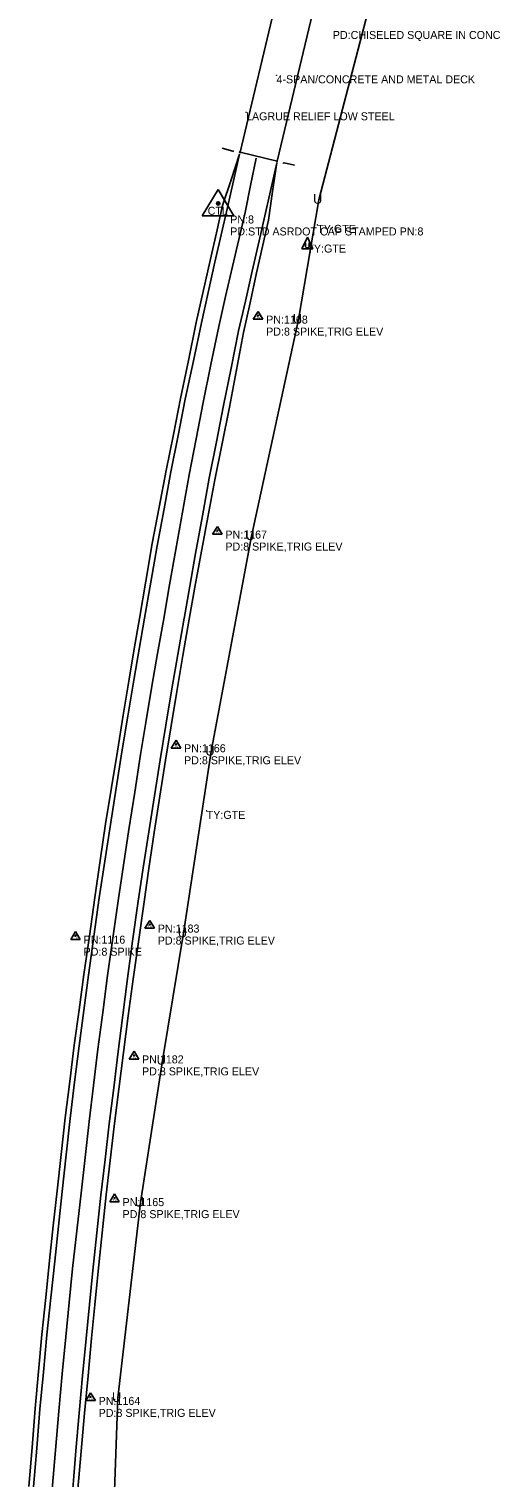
# Model space of a CAD drawing. Extents: x 1445297 to 1476720, y 2042269 to 2057889.
# Drawn here: x 1445689 to 1445983, y 2053749 to 2054654 of the extents above; entities that cross this region are included whole.
import ezdxf

# ---------------------------------------------------------------- set-up
doc = ezdxf.new("R2010")
doc.units = 0
for name, color, linetype in [('S_BRIDGE', 7, 'Continuous'), ('S_EDGE_PAVEMENT', 7, 'Continuous'), ('S_FIBER_OPTIC_CABLE_ANNOT', 7, 'Continuous'), ('S_MSC_PT_SYM', 7, 'Continuous'), ('S_PAVEMENT_CROWN', 7, 'Continuous'), ('S_PRIMARY_CTL', 7, 'Continuous'), ('S_PRIMARY_CTL_ANNOT', 7, 'Continuous'), ('S_SECONDARY_CTL', 7, 'Continuous'), ('S_SECONDARY_CTL_ANNOT', 7, 'Continuous'), ('S_SHOULDER', 7, 'Continuous'), ('S_STR_PT_SYM', 7, 'Continuous'), ('S_SURVEY_TEXT_ANNOT', 7, 'Continuous'), ('S_UNDERGROUND_CABLE', 7, 'Continuous'), ('S_UTILITY_POLE', 7, 'Continuous'), ('S_UTILITY_POLE_ANNOT', 7, 'Continuous'), ('S_UTL_PT_SYM', 7, 'Continuous'), ('S_WALL', 7, 'Continuous')]:
    doc.layers.add(name, color=color, linetype=linetype)

msp = doc.modelspace()

# ---------------------------------------------------------------- linework, layer by layer
at = {"layer": 'S_BRIDGE'}
for p, q in [((1445820.81, 2054577.05), (1445844.02, 2054674.24)), ((1445867.36, 2054668.87), (1445844.01, 2054571.43)), ((1445844.01, 2054571.43), (1445820.81, 2054577.05))]:
    msp.add_line(p, q, dxfattribs=at)
at = {"layer": 'S_EDGE_PAVEMENT'}
for points in [[(1445691.76, 2053742.83), (1445693.79, 2053767.11), (1445695.82, 2053791.4), (1445698.01, 2053814.6), (1445700.19, 2053837.81), (1445702.62, 2053860.93), (1445705.04, 2053884.05), (1445707.31, 2053905.74), (1445709.58, 2053927.43), (1445712.13, 2053950.31), (1445714.68, 2053973.19), (1445717.46, 2053995.81), (1445720.23, 2054018.42), (1445723.13, 2054040.58), (1445726.03, 2054062.73), (1445729.45, 2054086.9), (1445732.86, 2054111.06), (1445736.35, 2054133.98), (1445739.85, 2054156.89), (1445743.42, 2054179.52), (1445746.99, 2054202.16), (1445750.74, 2054224.55), (1445754.48, 2054246.94), (1445757.79, 2054266.34), (1445761.09, 2054285.73), (1445765.04, 2054308.35), (1445768.99, 2054330.97), (1445773.31, 2054354.13), (1445777.62, 2054377.29), (1445782.09, 2054399.97), (1445786.57, 2054422.64), (1445791.69, 2054446.54), (1445796.81, 2054470.43), (1445800.94, 2054489.32), (1445805.06, 2054508.2), (1445808.99, 2054525.32), (1445812.92, 2054542.44), (1445816.72, 2054559.08), (1445820.53, 2054575.72)], [(1445716.28, 2053741.76), (1445718.26, 2053765.38), (1445720.25, 2053788.99), (1445722.45, 2053812.32), (1445724.66, 2053835.65), (1445726.77, 2053856.9), (1445728.89, 2053878.15), (1445731.41, 2053901.64), (1445733.92, 2053925.12), (1445736.5, 2053947.43), (1445739.07, 2053969.74), (1445741.86, 2053992.34), (1445744.65, 2054014.94), (1445747.53, 2054037.75), (1445750.41, 2054060.55), (1445753.68, 2054084.02), (1445756.94, 2054107.48), (1445760.33, 2054129.83), (1445763.73, 2054152.17), (1445767.28, 2054174.76), (1445770.84, 2054197.34), (1445774.46, 2054218.89), (1445778.09, 2054240.44), (1445781.98, 2054263.07), (1445785.88, 2054285.69), (1445785.88, 2054285.51), (1445789.47, 2054305.86), (1445793.06, 2054326.22), (1445797.32, 2054349.71), (1445801.57, 2054373.2), (1445806.02, 2054395.94), (1445810.46, 2054418.68), (1445815.19, 2054441.98), (1445819.93, 2054465.28), (1445824.21, 2054483.92), (1445828.49, 2054502.57), (1445832.23, 2054518.93), (1445835.97, 2054535.29), (1445839.85, 2054552.8), (1445843.73, 2054570.31)]]:
    msp.add_lwpolyline(points, dxfattribs=at)
at = {"layer": 'S_MSC_PT_SYM'}
for points in [[(1445843.6, 2054625.03), (1445843.6, 2054625.08), (1445843.6, 2054625.03), (1445843.55, 2054625.03), (1445843.6, 2054625.03), (1445843.6, 2054624.98), (1445843.6, 2054625.03), (1445843.65, 2054625.03)], [(1445824.57, 2054601.93), (1445824.57, 2054601.98), (1445824.57, 2054601.93), (1445824.52, 2054601.93), (1445824.57, 2054601.93), (1445824.57, 2054601.88), (1445824.57, 2054601.93), (1445824.62, 2054601.93)]]:
    msp.add_lwpolyline(points, dxfattribs=at)
at = {"layer": 'S_PAVEMENT_CROWN'}
msp.add_lwpolyline([(1445703.34, 2053741.56), (1445705.43, 2053765.89), (1445707.51, 2053790.22), (1445709.73, 2053813.46), (1445711.95, 2053836.7), (1445714.04, 2053858.03), (1445716.12, 2053879.35), (1445718.79, 2053902.87), (1445721.46, 2053926.38), (1445723.99, 2053948.75), (1445726.53, 2053971.13), (1445729.22, 2053993.76), (1445731.92, 2054016.4), (1445734.99, 2054039.43), (1445738.06, 2054062.47), (1445741.35, 2054085.76), (1445744.65, 2054109.05), (1445747.97, 2054131.36), (1445751.28, 2054153.67), (1445754.99, 2054177.09), (1445758.69, 2054200.5), (1445762.18, 2054221.87), (1445765.67, 2054243.23), (1445769.32, 2054263.74), (1445772.97, 2054284.25), (1445776.79, 2054306.53), (1445780.61, 2054328.8), (1445784.86, 2054352.04), (1445789.11, 2054375.29), (1445793.45, 2054397.89), (1445797.79, 2054420.5), (1445802.67, 2054444.25), (1445807.54, 2054468), (1445811.79, 2054486.77), (1445816.03, 2054505.54), (1445819.99, 2054522.37), (1445823.94, 2054539.2), (1445827.38, 2054556.24), (1445830.82, 2054573.28)], dxfattribs=at)
at = {"layer": 'S_PRIMARY_CTL'}
for p, q in [((1445807.18, 2054553.65), (1445797.14, 2054537.14)), ((1445807.18, 2054553.65), (1445817, 2054537.14)), ((1445797.14, 2054537.14), (1445817, 2054537.14))]:
    msp.add_line(p, q, dxfattribs=at)
for radius in [1.04, 0.609, 0.344]:
    msp.add_circle((1445807.18, 2054544.95), radius, dxfattribs=at)
at = {"layer": 'S_SECONDARY_CTL'}
for p, q in [((1445832.14, 2054477.5), (1445829.13, 2054472.55)), ((1445832.14, 2054477.5), (1445835.08, 2054472.55)), ((1445829.13, 2054472.55), (1445835.08, 2054472.55)), ((1445806.66, 2054343.15), (1445803.65, 2054338.2)), ((1445806.66, 2054343.15), (1445809.61, 2054338.2)), ((1445803.65, 2054338.2), (1445809.61, 2054338.2)), ((1445780.83, 2054209.59), (1445777.82, 2054204.64)), ((1445780.83, 2054209.59), (1445783.77, 2054204.64)), ((1445777.82, 2054204.64), (1445783.77, 2054204.64)), ((1445764.43, 2054096.92), (1445761.42, 2054091.97)), ((1445764.43, 2054096.92), (1445767.38, 2054091.97)), ((1445718.06, 2054089.97), (1445715.05, 2054085.01)), ((1445718.06, 2054089.97), (1445721.01, 2054085.01)), ((1445761.42, 2054091.97), (1445767.38, 2054091.97)), ((1445715.05, 2054085.01), (1445721.01, 2054085.01)), ((1445754.58, 2054015.16), (1445751.57, 2054010.21)), ((1445754.58, 2054015.16), (1445757.53, 2054010.21)), ((1445751.57, 2054010.21), (1445757.53, 2054010.21)), ((1445742.4, 2053925.95), (1445739.39, 2053921)), ((1445742.4, 2053925.95), (1445745.35, 2053921)), ((1445739.39, 2053921), (1445745.35, 2053921)), ((1445727.46, 2053801.74), (1445724.45, 2053796.79)), ((1445727.46, 2053801.74), (1445730.41, 2053796.79)), ((1445724.45, 2053796.79), (1445730.41, 2053796.79))]:
    msp.add_line(p, q, dxfattribs=at)
for centre, radius in [((1445832.14, 2054474.89), 0.311), ((1445832.14, 2054474.89), 0.183), ((1445832.14, 2054474.89), 0.103), ((1445806.66, 2054340.54), 0.311), ((1445806.66, 2054340.54), 0.183), ((1445806.66, 2054340.54), 0.103), ((1445780.83, 2054206.98), 0.311), ((1445780.83, 2054206.98), 0.183), ((1445780.83, 2054206.98), 0.103), ((1445718.06, 2054087.36), 0.311), ((1445718.06, 2054087.36), 0.183), ((1445718.06, 2054087.36), 0.103), ((1445764.43, 2054094.31), 0.311), ((1445764.43, 2054094.31), 0.183), ((1445764.43, 2054094.31), 0.103), ((1445754.58, 2054012.55), 0.311), ((1445754.58, 2054012.55), 0.183), ((1445754.58, 2054012.55), 0.103), ((1445742.4, 2053923.34), 0.311), ((1445742.4, 2053923.34), 0.183), ((1445742.4, 2053923.34), 0.103), ((1445727.46, 2053799.13), 0.311), ((1445727.46, 2053799.13), 0.183), ((1445727.46, 2053799.13), 0.103)]:
    msp.add_circle(centre, radius, dxfattribs=at)
at = {"layer": 'S_SHOULDER'}
for points in [[(1445688.92, 2053743.09), (1445690.9, 2053767.46), (1445692.87, 2053791.84), (1445694.95, 2053814.95), (1445697.04, 2053838.06), (1445699.4, 2053861.24), (1445701.77, 2053884.42), (1445704.11, 2053906.12), (1445706.46, 2053927.81), (1445709.02, 2053950.68), (1445711.57, 2053973.55), (1445714.38, 2053996.19), (1445717.19, 2054018.84), (1445720.23, 2054040.92), (1445723.28, 2054063), (1445726.68, 2054087.14), (1445730.07, 2054111.29), (1445733.44, 2054134.32), (1445736.81, 2054157.34), (1445740.49, 2054180.06), (1445744.16, 2054202.77), (1445747.85, 2054225.17), (1445751.54, 2054247.57), (1445754.73, 2054266.56), (1445757.93, 2054285.54), (1445761.96, 2054308.98), (1445765.98, 2054332.42), (1445770.34, 2054355.25), (1445774.7, 2054378.08), (1445779.2, 2054400.61), (1445783.71, 2054423.14), (1445788.53, 2054446.82), (1445793.36, 2054470.5), (1445797.72, 2054489.9), (1445802.08, 2054509.3), (1445806.02, 2054526.54), (1445809.97, 2054543.78), (1445815.25, 2054559.75), (1445820.53, 2054575.72)], [(1445719.56, 2053741.42), (1445721.59, 2053765.14), (1445723.62, 2053788.86), (1445725.84, 2053812.3), (1445728.06, 2053835.73), (1445730.08, 2053856.75), (1445732.09, 2053877.77), (1445734.62, 2053901.63), (1445737.15, 2053925.5), (1445739.65, 2053946.91), (1445742.15, 2053968.32), (1445745.03, 2053991.37), (1445747.92, 2054014.42), (1445750.98, 2054037.27), (1445754.05, 2054060.11), (1445757.34, 2054083.59), (1445760.63, 2054107.07), (1445763.91, 2054129.42), (1445767.18, 2054151.77), (1445770.68, 2054174.46), (1445774.17, 2054197.14), (1445777.75, 2054218.57), (1445781.34, 2054239.99), (1445785.14, 2054262.54), (1445788.94, 2054285.1), (1445792.65, 2054305.25), (1445796.36, 2054325.39), (1445800.68, 2054348.84), (1445805, 2054372.29), (1445809.67, 2054394.98), (1445814.33, 2054417.66), (1445818.71, 2054440.96), (1445823.09, 2054464.25), (1445827.11, 2054482.89), (1445831.13, 2054501.52), (1445834.9, 2054518.04), (1445838.67, 2054534.56), (1445841.2, 2054552.44), (1445843.73, 2054570.31)]]:
    msp.add_lwpolyline(points, dxfattribs=at)
at = {"layer": 'S_STR_PT_SYM'}
for points in [[(1445820.81, 2054577.05), (1445820.81, 2054577.55), (1445820.81, 2054577.05), (1445820.31, 2054577.05), (1445820.81, 2054577.05), (1445820.81, 2054576.55), (1445820.81, 2054577.05), (1445821.31, 2054577.05)], [(1445844.01, 2054571.43), (1445844.01, 2054571.93), (1445844.01, 2054571.43), (1445843.51, 2054571.43), (1445844.01, 2054571.43), (1445844.01, 2054570.93), (1445844.01, 2054571.43), (1445844.51, 2054571.43)]]:
    msp.add_lwpolyline(points, dxfattribs=at)
at = {"layer": 'S_UNDERGROUND_CABLE'}
for p, q in [((1445870.09, 2054547.32), (1445935.62, 2054798.44)), ((1445857.39, 2054472.48), (1445870.09, 2054547.32)), ((1445827.89, 2054337.12), (1445857.39, 2054472.48)), ((1445802.76, 2054202.49), (1445827.89, 2054337.12)), ((1445785.57, 2054088.88), (1445802.76, 2054202.49)), ((1445772.33, 2054009.33), (1445785.57, 2054088.88)), ((1445758.69, 2053920.52), (1445772.33, 2054009.33)), ((1445744.38, 2053798.49), (1445758.69, 2053920.52)), ((1445735.77, 2053556.65), (1445744.38, 2053798.49))]:
    msp.add_line(p, q, dxfattribs=at)
at = {"layer": 'S_UTILITY_POLE'}
for p, q in [((1445862.89, 2054523.79), (1445859.37, 2054516.7)), ((1445862.89, 2054523.79), (1445866.38, 2054516.7)), ((1445859.37, 2054516.7), (1445866.38, 2054516.7)), ((1445861.69, 2054517.94), (1445861.69, 2054520.38)), ((1445862.31, 2054517.28), (1445861.69, 2054517.94)), ((1445863.51, 2054517.28), (1445862.31, 2054517.28)), ((1445864.06, 2054517.94), (1445863.51, 2054517.28)), ((1445864.06, 2054520.38), (1445864.06, 2054517.94))]:
    msp.add_line(p, q, dxfattribs=at)
at = {"layer": 'S_UTL_PT_SYM'}
for points in [[(1445869.1, 2054531.57), (1445869.1, 2054531.62), (1445869.1, 2054531.57), (1445869.05, 2054531.57), (1445869.1, 2054531.57), (1445869.1, 2054531.52), (1445869.1, 2054531.57), (1445869.15, 2054531.57)], [(1445799.99, 2054165.36), (1445799.99, 2054165.41), (1445799.99, 2054165.36), (1445799.94, 2054165.36), (1445799.99, 2054165.36), (1445799.99, 2054165.31), (1445799.99, 2054165.36), (1445800.04, 2054165.36)]]:
    msp.add_lwpolyline(points, dxfattribs=at)
at = {"layer": 'S_WALL'}
for points in [[(1445809.74, 2054579.54), (1445816.39, 2054577.68), (1445816.5, 2054577.7), (1445817.01, 2054577.48)], [(1445847.63, 2054570.4), (1445848.14, 2054570.23), (1445848.34, 2054570.29), (1445854.84, 2054568.78)]]:
    msp.add_lwpolyline(points, dxfattribs=at)

# ---------------------------------------------------------------- texts
at = {"layer": 'S_FIBER_OPTIC_CABLE_ANNOT'}
for p in [(1445869.1, 2054526.57), (1445799.99, 2054160.36)]:
    msp.add_text('TY:GTE', height=5, dxfattribs=at).set_placement(p)
at = {"layer": 'S_PRIMARY_CTL'}
msp.add_text('CTL', height=5, dxfattribs=at).set_placement((1445800.59, 2054537.88))
at = {"layer": 'S_PRIMARY_CTL_ANNOT'}
for s, p in [('PD:CHISELED SQUARE IN CONC', (1445878.79, 2054647.75)), ('PN:8', (1445814.68, 2054532.45)), ('PD:STD ASRDOT CAP STAMPED PN:8', (1445814.68, 2054524.95))]:
    msp.add_text(s, height=5, dxfattribs=at).set_placement(p)
at = {"layer": 'S_SECONDARY_CTL'}
for p in [(1445830.93, 2054472.88), (1445805.45, 2054338.53), (1445779.62, 2054204.97), (1445763.22, 2054092.3), (1445716.86, 2054085.35), (1445753.37, 2054010.54), (1445741.2, 2053921.33), (1445726.25, 2053797.12)]:
    msp.add_text('TV', height=1.5, dxfattribs=at).set_placement(p)
at = {"layer": 'S_SECONDARY_CTL_ANNOT'}
for s, p in [('PN:1168', (1445837.14, 2054469.89)), ('PD:8 SPIKE,TRIG ELEV', (1445837.14, 2054462.39)), ('PN:1167', (1445811.66, 2054335.54)), ('PD:8 SPIKE,TRIG ELEV', (1445811.66, 2054328.04)), ('PN:1166', (1445785.83, 2054201.98)), ('PD:8 SPIKE,TRIG ELEV', (1445785.83, 2054194.48)), ('PN:1116', (1445723.06, 2054082.36)), ('PN:1183', (1445769.43, 2054089.31)), ('PD:8 SPIKE', (1445723.06, 2054074.86)), ('PD:8 SPIKE,TRIG ELEV', (1445769.43, 2054081.81)), ('PN:1182', (1445759.58, 2054007.55)), ('PD:8 SPIKE,TRIG ELEV', (1445759.58, 2054000.05)), ('PN:1165', (1445747.4, 2053918.34)), ('PD:8 SPIKE,TRIG ELEV', (1445747.4, 2053910.84)), ('PN:1164', (1445732.46, 2053794.13)), ('PD:8 SPIKE,TRIG ELEV', (1445732.46, 2053786.63))]:
    msp.add_text(s, height=5, dxfattribs=at).set_placement(p)
at = {"layer": 'S_SURVEY_TEXT_ANNOT'}
for s, p in [('4-SPAN/CONCRETE AND METAL DECK ', (1445843.6, 2054620.03)), ('LAGRUE RELIEF LOW STEEL', (1445824.57, 2054596.93))]:
    msp.add_text(s, height=5, dxfattribs=at).set_placement(p)
at = {"layer": 'S_UTILITY_POLE_ANNOT'}
msp.add_text('TY:GTE', height=5, dxfattribs=at).set_placement((1445862.89, 2054514.26))
at = {"layer": 'S_UTL_PT_SYM'}
for p in [(1445866.46, 2054544.78), (1445853.76, 2054469.93), (1445824.27, 2054334.58), (1445799.13, 2054199.94), (1445781.94, 2054086.34), (1445768.7, 2054006.78), (1445755.06, 2053917.97), (1445740.75, 2053795.95)]:
    msp.add_text('U', height=6, dxfattribs=at).set_placement(p)

doc.saveas('drawing.dxf')
